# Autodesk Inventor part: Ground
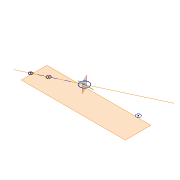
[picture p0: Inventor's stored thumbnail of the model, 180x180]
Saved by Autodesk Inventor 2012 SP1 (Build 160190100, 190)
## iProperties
Created: 2006-09
Part Number: Ground
Document SubType Name: Modeling
Density: 1 g/cm^3
Material: Default
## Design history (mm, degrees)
sketch "Sketch1"
  geometry: L1 (-14.96, 0)-(19.946, 0) reference; L2 (0, 0)-(-76.173, -35.52); C1 r 10 at (0, 0); C2 r 5 at (120, 0); C3 r 4.211 at (-54.378, -25.357); C4 r 3.827 at (-81.568, -38.036); 1 further point
  constraints: 4 centre point, 3 point on line, 2 end point, 1 coincident
  dimensions: "d0" = 120 distance of C2.centre point (0, 0); "d1" = 20 diameter of C1; "d2" = 10 diameter of C2; "d3" = 60 distance of C3.centre point (0, 0); "d4" = 90 distance of point (0, 0) C4.centre; "d5" = 25 deg angle of L2 L1
workplane "Work Plane1"
  workaxis "Work Axis1"
workplane "Work Plane2"
other parameters: "d6" = -17.25
